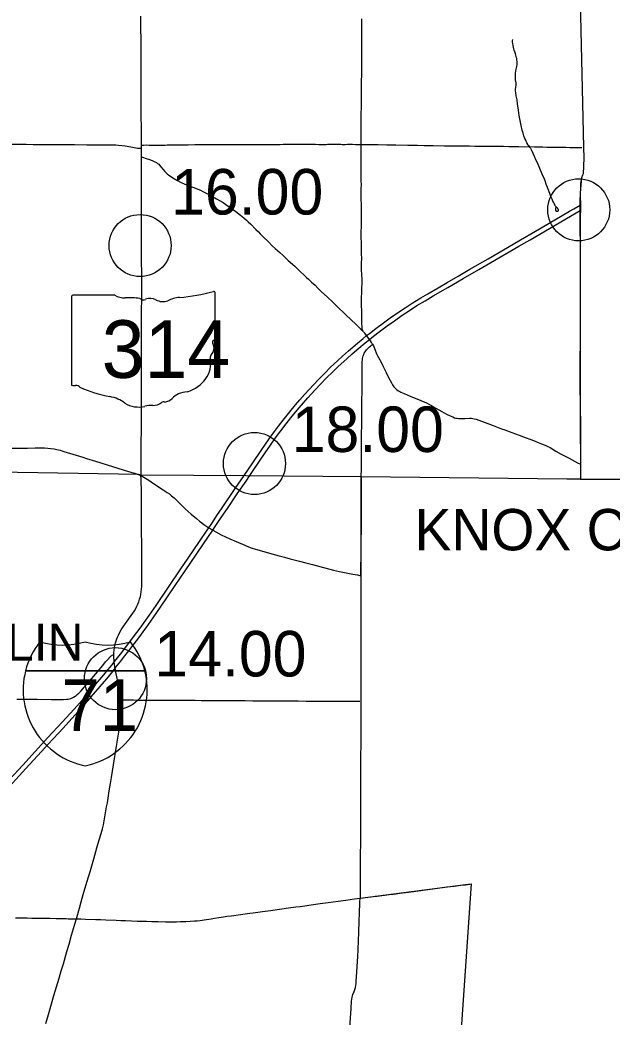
# Model space of a CAD drawing. Extents: x 1813937 to 1948437, y 826606 to 1022856.
# Drawn here: x 1920560 to 1934882, y 915824 to 939932 of the extents above; entities that cross this region are included whole.
import ezdxf

# ---------------------------------------------------------------- set-up
doc = ezdxf.new("R2010")
doc.units = 0
for name, color, linetype in [('Default', 7, 'Continuous'), ('GM_X_Adjacent_County', 7, 'Continuous'), ('GM_X_Adjacent_County_Text', 7, 'Continuous'), ('GM_X_County', 7, 'Continuous'), ('GM_X_County_Road', 7, 'Continuous'), ('GM_X_Interstate_Route', 7, 'Continuous'), ('GM_X_Interstate_Shield', 7, 'Continuous'), ('GM_X_State_Route', 7, 'Continuous'), ('GM_X_State_Shield', 7, 'Continuous'), ('GM_X_Township', 7, 'Continuous'), ('GM_X_Township_Road', 7, 'Continuous'), ('GM_X_Township_Text', 7, 'Continuous')]:
    doc.layers.add(name, color=color, linetype=linetype)

msp = doc.modelspace()

# ---------------------------------------------------------------- linework, layer by layer
at = {"layer": 'Default'}
for centre in [(1934076, 935341), (1923466, 934478), (1926233, 929208), (1922870, 924006)]:
    msp.add_circle(centre, 750, dxfattribs=at)
at = {"layer": 'GM_X_Adjacent_County'}
msp.add_line((1934122, 928828), (1943305, 928835), dxfattribs=at)
at = {"layer": 'GM_X_County'}
msp.add_lwpolyline([(1934067, 942157), (1934195, 936859), (1934202, 936590), (1934187, 936214), (1934165, 936177), (1934141, 936112), (1934134, 936040), (1934113, 935746), (1934115, 935394), (1934114, 935137), (1934107, 931513), (1934121, 929197), (1934122, 928828), (1933789, 928831), (1928810, 928882), (1928810, 928443), (1928806, 926508), (1928802, 923466), (1928787, 918701), (1931337, 919032), (1931473, 919044), (1931168, 914595)], dxfattribs=at)
at = {"layer": 'GM_X_County_Road'}
for points in [[(1928857, 932416), (1928853, 932423), (1928846, 932439), (1928840, 932455), (1928837, 932472), (1928834, 932505), (1928831, 932603), (1928831, 932686), (1928832, 932784), (1928829, 932882), (1928822, 933046), (1928822, 933128), (1928824, 933211), (1928828, 933342), (1928829, 933406), (1928834, 933615), (1928835, 933681), (1928833, 933763), (1928824, 933910), (1928824, 933976), (1928824, 934058), (1928826, 934156), (1928824, 934287), (1928820, 934402), (1928819, 934517), (1928816, 934697), (1928816, 934798), (1928818, 934944), (1928818, 935027), (1928819, 935173), (1928821, 935370), (1928820, 935452), (1928817, 935615), (1928816, 935697), (1928816, 935812), (1928817, 935878), (1928818, 935927), (1928816, 936057), (1928817, 936106), (1928815, 936187), (1928814, 936253), (1928815, 936338), (1928814, 936398), (1928814, 936484), (1928814, 936548), (1928813, 936617), (1928815, 936711), (1928813, 936793), (1928811, 936857), (1928812, 936921)], [(1929084, 932092), (1929079, 932103), (1929073, 932118), (1929066, 932132), (1929040, 932173), (1929014, 932209), (1929002, 932227), (1928946, 932299), (1928902, 932357), (1928871, 932395), (1928861, 932409), (1928857, 932416)], [(1928817, 928861), (1928819, 929108), (1928819, 929239), (1928821, 929519), (1928823, 929666), (1928824, 929814), (1928825, 929978), (1928826, 930076), (1928827, 930158), (1928827, 930289), (1928828, 930437), (1928830, 930617), (1928832, 930781), (1928834, 930912), (1928835, 931043), (1928837, 931207), (1928836, 931372), (1928836, 931470), (1928838, 931602), (1928841, 931667), (1928845, 931717), (1928849, 931750), (1928856, 931782), (1928865, 931814), (1928877, 931845), (1928890, 931875), (1928907, 931904), (1928926, 931932), (1928946, 931958), (1928968, 931983), (1928992, 932006), (1929016, 932028), (1929041, 932048), (1929055, 932059), (1929067, 932068), (1929077, 932076), (1929084, 932092)], [(1920034, 929595), (1920073, 929590), (1920155, 929583), (1920368, 929581), (1920582, 929580), (1920745, 929581), (1920926, 929583), (1921057, 929585), (1921156, 929583), (1921238, 929578), (1921303, 929571), (1921385, 929560), (1921449, 929547), (1921529, 929527), (1921624, 929501), (1921922, 929409), (1922078, 929360), (1922172, 929329), (1922391, 929261), (1922798, 929135), (1922924, 929096), (1923081, 929049), (1923321, 928978), (1923337, 928973)], [(1923337, 928973), (1923394, 928953), (1923487, 928919)], [(1923487, 928919), (1923520, 928902), (1923600, 928855), (1923677, 928807), (1923793, 928726), (1924026, 928572), (1924122, 928509), (1924175, 928471), (1924227, 928430), (1924289, 928377), (1924338, 928332), (1924560, 928114), (1924632, 928047), (1924705, 927981), (1924830, 927875), (1924905, 927813), (1924957, 927773), (1925009, 927733), (1925036, 927714), (1925127, 927655), (1925131, 927652), (1925201, 927609), (1925224, 927597), (1925302, 927553), (1925431, 927486), (1925533, 927437), (1925638, 927390), (1925789, 927326), (1925999, 927232), (1926090, 927194), (1926151, 927172), (1926261, 927138), (1926513, 927065), (1926655, 927025), (1926829, 926978), (1926956, 926945), (1927098, 926906), (1927320, 926845), (1927478, 926804), (1927637, 926763), (1927811, 926716), (1928145, 926630), (1928289, 926597), (1928449, 926564), (1928610, 926534), (1928723, 926513), (1928807, 926493)], [(1928807, 926493), (1928809, 926621), (1928809, 926752), (1928812, 926899), (1928813, 926997), (1928812, 927177), (1928812, 927324), (1928811, 927487), (1928811, 927749), (1928813, 927847), (1928813, 928059), (1928812, 928190), (1928814, 928353), (1928815, 928468), (1928815, 928598), (1928816, 928761), (1928817, 928861)], [(1928786, 918696), (1928859, 918706), (1928908, 918712), (1928973, 918721), (1929054, 918732), (1929151, 918744), (1929199, 918750), (1929489, 918787), (1929586, 918799), (1929700, 918813), (1929814, 918828), (1929960, 918847), (1930139, 918870), (1930317, 918893), (1930545, 918924), (1930886, 918970), (1931065, 918992), (1931227, 919011), (1931335, 919024)], [(1931335, 919024), (1931443, 919037)], [(1921924, 918198), (1921946, 918198), (1922036, 918196), (1922149, 918193), (1922394, 918183), (1922509, 918179), (1922640, 918174), (1922886, 918164), (1923000, 918159), (1923115, 918156), (1923262, 918151), (1923393, 918146), (1923508, 918143), (1923622, 918140), (1923753, 918136), (1923901, 918132), (1924081, 918128), (1924196, 918127), (1924343, 918130), (1924441, 918132), (1924572, 918135), (1924676, 918141), (1924785, 918148), (1924845, 918153), (1924921, 918162), (1925019, 918175), (1925186, 918201), (1925264, 918213), (1925367, 918230), (1925484, 918248), (1925568, 918261), (1925680, 918275), (1925891, 918304), (1926118, 918334), (1926198, 918346), (1926425, 918377), (1926555, 918395), (1926620, 918404), (1926896, 918441), (1927059, 918463), (1927237, 918487), (1927335, 918501), (1927448, 918517), (1927546, 918531), (1927822, 918568), (1928017, 918594), (1928261, 918627), (1928439, 918650), (1928654, 918679), (1928720, 918688), (1928786, 918696)], [(1920455, 918223), (1920685, 918220), (1920701, 918220), (1920736, 918220), (1920849, 918218), (1920992, 918217), (1921119, 918217), (1921201, 918216)], [(1921201, 918216), (1921285, 918215), (1921436, 918210), (1921597, 918206), (1921676, 918204), (1921724, 918202), (1921838, 918199), (1921887, 918198), (1921924, 918198)]]:
    msp.add_lwpolyline(points, dxfattribs=at)
at = {"layer": 'GM_X_Interstate_Route'}
for points in [[(1920083, 921323), (1920626, 921916), (1920926, 922242), (1921237, 922580), (1921581, 922955), (1921869, 923269), (1922001, 923416), (1922208, 923649), (1922389, 923861), (1922589, 924100), (1922694, 924226), (1922736, 924277), (1922790, 924344), (1922808, 924366), (1922840, 924408), (1922848, 924418), (1922992, 924597), (1923122, 924766), (1923310, 925015), (1923465, 925227), (1923685, 925534), (1923854, 925776), (1924451, 926659), (1924627, 926916), (1924903, 927324), (1925087, 927595), (1925127, 927655), (1925216, 927785), (1925326, 927949), (1925455, 928138), (1925769, 928600), (1925984, 928918), (1926192, 929225), (1926395, 929523), (1926591, 929807), (1926696, 929953), (1926813, 930111), (1926924, 930254), (1927088, 930459), (1927224, 930623), (1927330, 930748), (1927450, 930882), (1927650, 931100), (1927796, 931255), (1927934, 931395), (1928075, 931533), (1928241, 931691), (1928362, 931802), (1928509, 931933), (1928721, 932115), (1928859, 932230), (1928946, 932299), (1929013, 932353), (1929169, 932474), (1929353, 932611), (1929512, 932726), (1929715, 932866), (1929878, 932975), (1930044, 933081), (1930253, 933211), (1930422, 933312), (1930678, 933459), (1930890, 933583), (1931160, 933740), (1931443, 933905), (1931883, 934160), (1932351, 934432), (1932664, 934614), (1933033, 934827), (1933501, 935100), (1933856, 935305), (1933956, 935362), (1934109, 935451)], [(1933740, 935107), (1933777, 935129), (1934110, 935322)], [(1932397, 934328), (1932628, 934462), (1932898, 934618), (1933365, 934892), (1933740, 935107)], [(1923602, 925224), (1923610, 925234), (1923780, 925475), (1923958, 925731), (1924317, 926260), (1924556, 926613), (1925118, 927441), (1925224, 927597), (1925284, 927685), (1925431, 927902), (1925578, 928120), (1925818, 928472), (1926030, 928784), (1926120, 928917), (1926205, 929042), (1926490, 929464), (1926620, 929653), (1926743, 929827), (1926870, 929999), (1926999, 930168), (1927112, 930310), (1927268, 930500), (1927416, 930675), (1927525, 930798), (1927691, 930980), (1927837, 931135), (1927975, 931276), (1928127, 931426), (1928258, 931551), (1928463, 931740), (1928597, 931860), (1928759, 932000), (1928910, 932126), (1929014, 932209), (1929115, 932290), (1929245, 932390), (1929443, 932537), (1929616, 932661), (1929805, 932792), (1929983, 932909), (1930163, 933024), (1930358, 933144), (1930556, 933261), (1930911, 933466), (1931280, 933680), (1931663, 933902), (1932145, 934183), (1932397, 934328)], [(1922210, 923480), (1922285, 923566), (1922499, 923814), (1922658, 924002), (1922804, 924181), (1922813, 924193), (1922863, 924257), (1922915, 924322), (1922967, 924390), (1923018, 924453), (1923095, 924555), (1923197, 924682), (1923267, 924774), (1923435, 924996), (1923602, 925224)], [(1918355, 919277), (1918695, 919648), (1918873, 919841), (1919085, 920069), (1919284, 920287), (1919561, 920590), (1920038, 921109), (1920316, 921410), (1920460, 921567), (1920703, 921834), (1921081, 922244), (1921237, 922413), (1921369, 922558), (1921602, 922812), (1921890, 923127), (1922122, 923381), (1922210, 923480)]]:
    msp.add_lwpolyline(points, dxfattribs=at)
at = {"layer": 'GM_X_Interstate_Shield'}
for p, q in [((1920695, 924195), (1923581, 924195)), ((1923581, 924195), (1920695, 924195)), ((1923581, 924195), (1920695, 924195))]:
    msp.add_line(p, q, dxfattribs=at)
for centre, start, end in [((1922513, 923735), 141.669, 165.8066), ((1921590, 926691), 253.0091, 286.9909), ((1922686, 926691), 253.0091, 286.9909), ((1921763, 923735), 14.1934, 38.331), ((1922513, 923735), 165.8066, 258.463), ((1921763, 923735), 281.537, 14.1934)]:
    msp.add_arc(centre, 1875, start, end, dxfattribs=at)
at = {"layer": 'GM_X_State_Route'}
for points in [[(1923508, 926469), (1923509, 926493), (1923508, 926592), (1923507, 926739), (1923507, 927001), (1923507, 927100), (1923506, 927215), (1923504, 927608), (1923502, 927952), (1923500, 928197), (1923498, 928443), (1923497, 928591), (1923492, 928756), (1923490, 928830), (1923487, 928919), (1923489, 928972), (1923490, 929003), (1923494, 929051), (1923494, 929150), (1923493, 929314), (1923494, 929511), (1923495, 929757), (1923497, 929970), (1923498, 930150), (1923497, 930265), (1923498, 930461), (1923498, 930690), (1923498, 930805), (1923499, 930969), (1923502, 931166), (1923503, 931280), (1923502, 931461), (1923501, 931674), (1923502, 931936), (1923501, 932181), (1923500, 932312), (1923501, 932493), (1923504, 932804), (1923504, 932968), (1923505, 933116), (1923505, 933313), (1923507, 933624), (1923506, 933772), (1923504, 934133), (1923503, 934281), (1923504, 934559), (1923503, 934723), (1923502, 934920), (1923504, 935199), (1923504, 935740), (1923504, 935921), (1923503, 936282), (1923503, 936479), (1923503, 936624), (1923503, 936725), (1923502, 936829), (1923502, 936889), (1923502, 936905), (1923502, 937053), (1923499, 937233), (1923497, 937397), (1923496, 937545), (1923494, 937774), (1923494, 938020), (1923493, 938282), (1923492, 938593), (1923491, 938724), (1923491, 939069), (1923490, 939217), (1923489, 939381), (1923486, 939807), (1923485, 940021)], [(1922964, 922819), (1922983, 922943), (1923010, 923122), (1923017, 923187), (1923021, 923252), (1923022, 923317), (1923020, 923382), (1923014, 923448), (1923008, 923495), (1923003, 923529), (1922975, 923690), (1922940, 923867), (1922888, 924124), (1922863, 924257), (1922858, 924285), (1922845, 924367), (1922840, 924408), (1922836, 924448), (1922832, 924514), (1922831, 924563), (1922832, 924593), (1922833, 924629), (1922839, 924695), (1922848, 924760), (1922856, 924809), (1922872, 924873), (1922885, 924920), (1922901, 924967), (1922919, 925013), (1922940, 925058), (1922969, 925116), (1923010, 925188), (1923054, 925257), (1923110, 925338), (1923293, 925590), (1923329, 925645), (1923361, 925701), (1923391, 925759), (1923411, 925804), (1923435, 925865), (1923455, 925927), (1923473, 925990), (1923484, 926037), (1923494, 926102), (1923502, 926166), (1923505, 926232), (1923508, 926395), (1923508, 926469)], [(1921187, 915666), (1921250, 915887), (1921383, 916343), (1921509, 916768), (1921560, 916941), (1921612, 917114), (1921697, 917413), (1921747, 917587), (1921810, 917807), (1921879, 918044), (1921924, 918198), (1921997, 918453), (1922043, 918611), (1922093, 918784), (1922181, 919082), (1922227, 919240), (1922263, 919366), (1922344, 919650), (1922422, 919917), (1922477, 920106), (1922523, 920263), (1922554, 920374), (1922577, 920469), (1922597, 920565), (1922623, 920710), (1922657, 920904), (1922674, 921000), (1922692, 921114), (1922720, 921292), (1922749, 921470), (1922772, 921616), (1922820, 921924), (1922892, 922377), (1922948, 922716), (1922964, 922819)]]:
    msp.add_lwpolyline(points, dxfattribs=at)
at = {"layer": 'GM_X_State_Shield'}
for p, q in [((1921804, 933242), (1921804, 931129)), ((1922857, 933278), (1921838, 933278)), ((1925284, 932225), (1925284, 933331)), ((1925284, 932225), (1925284, 932225))]:
    msp.add_line(p, q, dxfattribs=at)
for centre, major_axis, start_param, end_param in [((1921844, 933246), (40.3, 0), 1.712693, 3.28349), ((1923100, 933524), (391, 0), 4.042523, 4.731795), ((1924044, 936159), (3691, 0), 4.814394, 5.042369), ((1925246, 933335), (38.7, 0), 6.141152, 7.989035), ((1923230, 932092), (1404, 0), 1.404758, 1.657858), ((1923549, 933257), (113, 0), 3.836095, 5.185415), ((1923714, 933013), (235, 0), 0.950623, 2.079405), ((1924017, 933348), (282, 0), 4.081561, 5.145723), ((1924515, 932633), (743, 0), 1.699011, 2.107814), ((1925275, 932144), (60, 0), 1.883978, 3.671073), ((1924894, 932004), (360, 0), 5.934695, 6.695948), ((1925243, 932221), (41.5, 0), 5.05454, 6.418171), ((1925423, 931763), (262, 0), 2.387724, 3.262537), ((1924251, 931622), (923, 0), 5.101752, 6.440018), ((1921844, 931124), (40.7, 0), 3.00124, 4.508301), ((1921850, 931340), (310, 0), 4.665946, 4.897461), ((1921914, 931007), (112, 0), 0.519207, 1.627899), ((1923327, 932905), (2665, 0), 4.195997, 4.488961), ((1922532, 930179), (834, 0), 0.823519, 1.323587), ((1924640, 930535), (506, 0), 1.647645, 2.488434), ((1923434, 930996), (529, 0), 4.026481, 4.996735), ((1923740, 930266), (435, 0), 1.495662, 1.94098), ((1923779, 930838), (282, 0), 4.691044, 5.507374), ((1924034, 930633), (79.4, 0), 1.147584, 2.315152), ((1924000, 930924), (298, 0), 4.937069, 5.64225)]:
    msp.add_ellipse(centre, major_axis=major_axis, ratio=0.8, start_param=start_param, end_param=end_param, dxfattribs=at)
at = {"layer": 'GM_X_Township'}
msp.add_lwpolyline([(1928810, 928882), (1926026, 928906), (1923489, 928928), (1923428, 928941), (1920005, 929002), (1917092, 929034), (1915316, 929031)], dxfattribs=at)
at = {"layer": 'GM_X_Township_Road'}
for points in [[(1928812, 936921), (1928812, 937110), (1928812, 937196), (1928811, 937280), (1928813, 937473), (1928815, 937603), (1928817, 937683), (1928819, 937798), (1928819, 937863), (1928820, 937978), (1928821, 938060), (1928822, 938174), (1928824, 938437), (1928827, 938633), (1928827, 938765), (1928827, 938912), (1928828, 939093), (1928830, 939322), (1928832, 939502), (1928830, 939649), (1928829, 939845), (1928829, 939960)], [(1932885, 936869), (1932856, 936899), (1932841, 936920), (1932819, 936963), (1932793, 937024), (1932774, 937069), (1932750, 937130), (1932729, 937192), (1932715, 937240), (1932707, 937271), (1932683, 937383), (1932668, 937464), (1932652, 937544), (1932636, 937625), (1932625, 937689), (1932616, 937754), (1932597, 937901), (1932583, 937998), (1932566, 938095), (1932554, 938175), (1932549, 938209), (1932549, 938227), (1932549, 938250), (1932555, 938306), (1932560, 938356), (1932562, 938388), (1932560, 938420), (1932555, 938435), (1932545, 938496), (1932544, 938546), (1932545, 938578), (1932547, 938595), (1932550, 938644), (1932556, 938693), (1932564, 938741), (1932576, 938806), (1932584, 938854), (1932586, 938887), (1932586, 938920), (1932582, 938969), (1932577, 939002), (1932574, 939018), (1932565, 939049), (1932554, 939080), (1932543, 939111), (1932529, 939158), (1932516, 939205), (1932509, 939236), (1932490, 939314), (1932481, 939362), (1932478, 939394), (1932477, 939426), (1932479, 939458)], [(1919484, 936943), (1919613, 936942), (1919794, 936941), (1919876, 936940), (1920040, 936937), (1920188, 936934), (1920368, 936931), (1920713, 936927), (1920877, 936923), (1920992, 936921), (1921107, 936921), (1921403, 936921), (1921666, 936920), (1921879, 936919), (1922174, 936916), (1922700, 936912), (1922880, 936910), (1922946, 936907), (1923028, 936899), (1923109, 936888), (1923239, 936866), (1923400, 936836), (1923449, 936829), (1923502, 936829)], [(1923502, 936905), (1923555, 936907), (1923620, 936909), (1923686, 936908), (1923862, 936908), (1924002, 936907), (1924073, 936907), (1924119, 936909), (1924150, 936910), (1924246, 936909), (1924314, 936910), (1924492, 936910), (1924557, 936913), (1924630, 936914), (1924788, 936917), (1924918, 936919), (1925002, 936919), (1925095, 936920), (1925190, 936923), (1925334, 936922), (1925423, 936923), (1925522, 936923), (1925621, 936921), (1925710, 936922), (1925824, 936920), (1925926, 936919), (1926029, 936921), (1926094, 936918), (1926175, 936920), (1926240, 936920), (1926289, 936919), (1926354, 936920), (1926484, 936922), (1926517, 936922), (1926582, 936922), (1926614, 936921), (1926695, 936921), (1926761, 936922), (1926810, 936922), (1926858, 936923), (1926924, 936925), (1926989, 936925), (1927153, 936926), (1927234, 936927), (1927316, 936928), (1927398, 936928), (1927627, 936925), (1927708, 936925), (1927791, 936923), (1927840, 936922), (1927905, 936924), (1927970, 936924), (1928003, 936925), (1928051, 936926), (1928083, 936926), (1928152, 936925), (1928252, 936926), (1928323, 936925), (1928353, 936924), (1928366, 936923), (1928391, 936922), (1928402, 936922), (1928428, 936923), (1928484, 936925), (1928605, 936925), (1928679, 936924), (1928749, 936922), (1928798, 936920), (1928812, 936921)], [(1928812, 936921), (1928880, 936922), (1928945, 936923), (1929060, 936921), (1929142, 936919), (1929224, 936918), (1929437, 936914), (1929650, 936911), (1929945, 936906), (1930076, 936904), (1930174, 936903), (1930338, 936900), (1930551, 936897), (1930830, 936892), (1931092, 936888), (1931305, 936885), (1931436, 936885), (1931567, 936884), (1931698, 936883), (1931829, 936881), (1931960, 936880), (1932156, 936879), (1932254, 936877), (1932385, 936874), (1932631, 936869), (1932762, 936868), (1932885, 936869)], [(1933514, 935398), (1933514, 935372), (1933513, 935356), (1933514, 935339), (1933516, 935331), (1933519, 935324), (1933525, 935318), (1933531, 935312), (1933541, 935308), (1933551, 935306), (1933560, 935307), (1933567, 935309), (1933574, 935312), (1933579, 935318), (1933583, 935323), (1933586, 935331), (1933587, 935339), (1933586, 935347), (1933583, 935354), (1933574, 935368), (1933564, 935381), (1933539, 935402), (1933527, 935414), (1933517, 935426), (1933509, 935440), (1933501, 935454), (1933494, 935467), (1933480, 935495), (1933467, 935524), (1933453, 935553), (1933433, 935598), (1933420, 935628), (1933413, 935643), (1933395, 935688), (1933378, 935734), (1933361, 935780), (1933338, 935842), (1933292, 935963), (1933262, 936039), (1933244, 936085), (1933194, 936206), (1933136, 936342), (1933076, 936477), (1933049, 936537), (1933009, 936627), (1932975, 936702), (1932935, 936792), (1932921, 936822), (1932913, 936836), (1932905, 936849), (1932885, 936869)], [(1932885, 936869), (1933007, 936867), (1933089, 936865), (1933204, 936862), (1933302, 936859), (1933482, 936858), (1933531, 936857), (1933597, 936857), (1933760, 936854), (1933859, 936852), (1934148, 936848)], [(1923503, 936624), (1923545, 936610), (1923592, 936594), (1923715, 936549), (1923776, 936525), (1923821, 936505), (1923864, 936482), (1923891, 936464), (1923904, 936454), (1923916, 936444), (1923939, 936420), (1923971, 936383), (1924022, 936319), (1924065, 936269), (1924098, 936233), (1924123, 936211), (1924161, 936180), (1924201, 936152), (1924257, 936117), (1924356, 936060), (1924456, 936005), (1924530, 935968), (1924590, 935942), (1924651, 935918), (1924744, 935886), (1924805, 935864), (1924866, 935841), (1924926, 935814), (1924985, 935786), (1925174, 935687), (1925318, 935608), (1925403, 935559), (1925473, 935516), (1925540, 935470), (1925701, 935356), (1925779, 935298), (1925896, 935209), (1925973, 935148), (1926036, 935095), (1926084, 935050), (1926142, 934993), (1926269, 934865), (1926327, 934808), (1926374, 934762), (1926443, 934692), (1926570, 934565), (1926663, 934473), (1926735, 934406), (1926844, 934307), (1926916, 934241), (1927048, 934118), (1927206, 933975), (1927267, 933920), (1927338, 933853), (1927446, 933752), (1927493, 933707), (1927541, 933662), (1927613, 933596), (1927697, 933518), (1927767, 933449), (1927848, 933369), (1927999, 933231), (1928119, 933116), (1928210, 933031), (1928454, 932793), (1928560, 932691), (1928690, 932566), (1928803, 932459), (1928857, 932416)], [(1934112, 935125), (1934113, 935200), (1934110, 935322), (1934108, 935381), (1934109, 935451), (1934110, 935576), (1934117, 935708), (1934123, 935873), (1934130, 935975), (1934142, 936067), (1934148, 936099)], [(1934109, 931509), (1934109, 931531), (1934112, 931695), (1934112, 931826), (1934115, 932039), (1934117, 932138), (1934118, 932203), (1934117, 932433), (1934117, 932597), (1934116, 932728), (1934115, 932826), (1934116, 932907), (1934116, 933104), (1934116, 933186), (1934117, 933301), (1934117, 933448), (1934116, 933596), (1934116, 933678), (1934116, 933792), (1934117, 933890), (1934117, 933972), (1934117, 934070), (1934118, 934168), (1934118, 934233), (1934115, 934598), (1934114, 934790), (1934114, 934914), (1934111, 935082), (1934112, 935125)], [(1929084, 932092), (1929108, 932051), (1929149, 931947), (1929174, 931886), (1929201, 931827), (1929231, 931768), (1929303, 931639), (1929348, 931552), (1929420, 931405), (1929485, 931273), (1929545, 931156), (1929569, 931113), (1929587, 931086), (1929607, 931060), (1929628, 931035), (1929651, 931012), (1929677, 930991), (1929717, 930963), (1929745, 930947), (1929775, 930932), (1929850, 930899), (1930002, 930838), (1930259, 930732), (1930395, 930674), (1930454, 930646), (1930511, 930614), (1930566, 930578), (1930622, 930545), (1930765, 930465), (1930881, 930404), (1930970, 930361), (1931029, 930334), (1931075, 930316), (1931107, 930307), (1931139, 930301), (1931171, 930297), (1931220, 930295), (1931319, 930298), (1931434, 930301), (1931483, 930300), (1931515, 930296), (1931547, 930290), (1931595, 930277), (1931657, 930257), (1931811, 930201), (1932010, 930125), (1932209, 930049), (1932286, 930020), (1932454, 929957), (1932639, 929889), (1932777, 929838), (1932915, 929785), (1933022, 929744), (1933098, 929715), (1933175, 929686), (1933281, 929643), (1933311, 929629), (1933383, 929591), (1933526, 929510), (1933654, 929437), (1933842, 929336), (1933970, 929264), (1934043, 929226), (1934118, 929190)], [(1934118, 929190), (1934123, 929206), (1934126, 929223), (1934127, 929256), (1934128, 929354), (1934127, 929419), (1934125, 929501), (1934123, 929599), (1934121, 929746), (1934119, 929943), (1934117, 930090), (1934116, 930253), (1934115, 930401), (1934116, 930515), (1934116, 930646), (1934115, 930793), (1934114, 930907), (1934111, 931201), (1934110, 931332), (1934109, 931447), (1934109, 931509)], [(1921723, 923511), (1921730, 923511), (1921762, 923518), (1921793, 923528), (1921823, 923540), (1921853, 923555), (1921895, 923580), (1921921, 923599), (1921947, 923620), (1921983, 923653), (1922039, 923713), (1922116, 923798), (1922201, 923898), (1922297, 924010), (1922561, 924324), (1922632, 924413), (1922676, 924463), (1922743, 924535), (1922766, 924557), (1922779, 924567), (1922794, 924575), (1922832, 924593)], [(1920484, 923508), (1920746, 923508), (1920976, 923507), (1921320, 923502), (1921517, 923500), (1921615, 923503), (1921697, 923507), (1921723, 923511)], [(1923008, 923495), (1923044, 923494), (1923143, 923492), (1923307, 923490), (1923405, 923489), (1923667, 923486), (1923782, 923486), (1924012, 923485), (1924258, 923483), (1924455, 923483), (1924619, 923482), (1924799, 923482), (1924947, 923480), (1925078, 923478), (1925242, 923477), (1925357, 923476), (1925472, 923475), (1925603, 923474), (1925651, 923475), (1925749, 923476), (1925847, 923477), (1926011, 923474), (1926192, 923471), (1926356, 923471), (1926471, 923469), (1926733, 923469), (1926848, 923469), (1927062, 923467), (1927193, 923466), (1927289, 923467), (1927487, 923465), (1927572, 923464), (1927635, 923464), (1927717, 923464), (1927831, 923464), (1927979, 923462), (1928143, 923460), (1928241, 923460), (1928340, 923461), (1928454, 923461), (1928585, 923460), (1928779, 923458)], [(1928538, 915569), (1928569, 916027), (1928582, 916207), (1928588, 916256), (1928596, 916304), (1928605, 916336), (1928615, 916367), (1928644, 916444), (1928660, 916490), (1928674, 916537), (1928684, 916586), (1928690, 916634), (1928696, 916700), (1928709, 916913), (1928717, 917044), (1928731, 917289), (1928740, 917453), (1928752, 917682), (1928759, 917862), (1928769, 918157), (1928775, 918321), (1928784, 918600), (1928786, 918696)]]:
    msp.add_lwpolyline(points, dxfattribs=at)

# ---------------------------------------------------------------- texts
at = {"layer": 'Default'}
for s, p in [('16.00', (1924216, 935228)), ('18.00', (1927133, 929486)), ('14.00', (1923810, 924059))]:
    msp.add_text(s, height=1100, dxfattribs=at).set_placement(p)
at = {"layer": 'GM_X_Adjacent_County_Text'}
msp.add_text('KNOX COUNTY', height=1000, dxfattribs=at).set_placement((1930105, 927108))
at = {"layer": 'GM_X_Interstate_Shield'}
msp.add_text('71', height=1250, dxfattribs=at).set_placement((1921560, 922741))
at = {"layer": 'GM_X_State_Shield'}
msp.add_text('314', height=1392.2, dxfattribs=at).set_placement((1922538, 931278))
at = {"layer": 'GM_X_Township_Text'}
msp.add_text('FRANKLIN', height=900, rotation=0, dxfattribs=at).set_placement((1916144, 924438))

doc.saveas('drawing.dxf')
